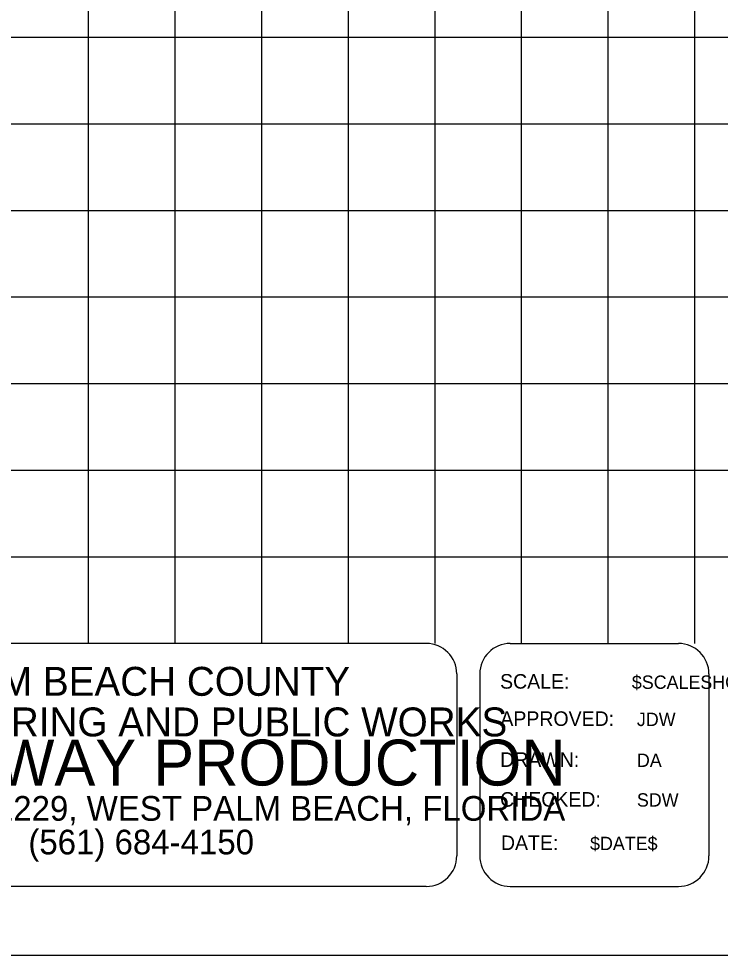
# Model space of a CAD drawing. Extents: x -4 to 16, y -3 to 9.7.
# Drawn here: x 10 to 12.024, y -0.9 to 1.803 of the extents above; entities that cross this region are included whole.
import ezdxf

# ---------------------------------------------------------------- set-up
doc = ezdxf.new("R2010")
doc.units = 0
for name, color, linetype in [('Baseline Bearing and Curve Data', 7, 'Continuous'), ('Centerline (Construction)', 7, 'Continuous'), ('Default', 7, 'Continuous'), ('Property Corners', 7, 'Continuous')]:
    doc.layers.add(name, color=color, linetype=linetype)

msp = doc.modelspace()

# ---------------------------------------------------------------- linework, layer by layer
at = {"layer": 'Baseline Bearing and Curve Data'}
for p, q in [((10.2, 4), (10.2, 0)), ((10.7, 4), (10.7, 0)), ((11.2, 4), (11.2, 0)), ((11.7, 4), (11.7, 0)), ((0, 1.5), (15.4, 1.5)), ((0, 1), (15.4, 1)), ((0, 0.5), (15.4, 0.5))]:
    msp.add_line(p, q, dxfattribs=at)
at = {"layer": 'Centerline (Construction)'}
msp.add_lwpolyline([(-0.55, -0.9), (15.95, -0.9), (15.95, 9.7), (-0.55, 9.7)], close=True, dxfattribs=at)
at = {"layer": 'Default'}
for p, q in [((11.1756, 0), (8.7497, 0)), ((11.4182, 0), (11.9034, 0)), ((11.2638, -0.0882), (11.2638, -0.6131)), ((11.33, -0.0882), (11.33, -0.6131)), ((11.9916, -0.0882), (11.9916, -0.6131)), ((11.1756, -0.7014), (8.7497, -0.7014)), ((11.4182, -0.7014), (11.9034, -0.7014))]:
    msp.add_line(p, q, dxfattribs=at)
for centre, major_axis, start_param, end_param in [((11.1756, -0.0882), (0, 0.0882), 4.712389, 6.283185), ((11.4182, -0.0882), (0, 0.0882), 0, 1.570796), ((11.9034, -0.0882), (0, 0.0882), 4.712389, 6.283185), ((11.1756, -0.6131), (0, 0.0882), 3.141593, 4.712389), ((11.4182, -0.6131), (0, -0.0882), 4.712389, 6.283185), ((11.9034, -0.6131), (0, -0.0882), 0, 1.570796)]:
    msp.add_ellipse(centre, major_axis=major_axis, ratio=0.999927, start_param=start_param, end_param=end_param, dxfattribs=at)
at = {"layer": 'Property Corners'}
for p, q in [((10.45, 4), (10.45, 0)), ((10.95, 4), (10.95, 0)), ((11.45, 4), (11.45, 0)), ((11.95, 4), (11.95, 0)), ((0.7, 1.75), (14.7, 1.75)), ((0.7, 1.25), (14.7, 1.25)), ((0.7, 0.75), (14.7, 0.75)), ((0.7, 0.25), (14.7, 0.25))]:
    msp.add_line(p, q, dxfattribs=at)

# ---------------------------------------------------------------- texts
at = {"layer": 'Default'}
for s, height, p in [('PALM BEACH COUNTY', 0.083446, (9.7345, -0.1511)), ('ENGINEERING AND PUBLIC WORKS', 0.083468, (9.4745, -0.2683)), ('ROADWAY PRODUCTION', 0.132369, (9.4241, -0.4101)), ('P.O. BOX 21229, WEST PALM BEACH, FLORIDA', 0.071224, (9.4333, -0.5117)), ('(561) 684-4150', 0.071224, (10.0274, -0.6088))]:
    msp.add_text(s, height=height, rotation=360, dxfattribs=at).set_placement(p)
for s, height, p in [('SCALE:', 0.04207, (11.3888, -0.1305)), ('$SCALESHORT$', 0.038546, (11.7691, -0.1311)), ('APPROVED:', 0.04207, (11.3896, -0.2381)), ('JDW', 0.03855, (11.7836, -0.2384)), ('DRAWN:', 0.04207, (11.389, -0.3563)), ('DA ', 0.03855, (11.7836, -0.3565)), ('CHECKED:', 0.04207, (11.3889, -0.4711)), ('SDW', 0.03855, (11.7836, -0.471)), ('DATE:', 0.04207, (11.3913, -0.5963)), ('$DATE$', 0.03855, (11.6484, -0.5965))]:
    msp.add_text(s, height=height, dxfattribs=at).set_placement(p)

doc.saveas('drawing.dxf')
